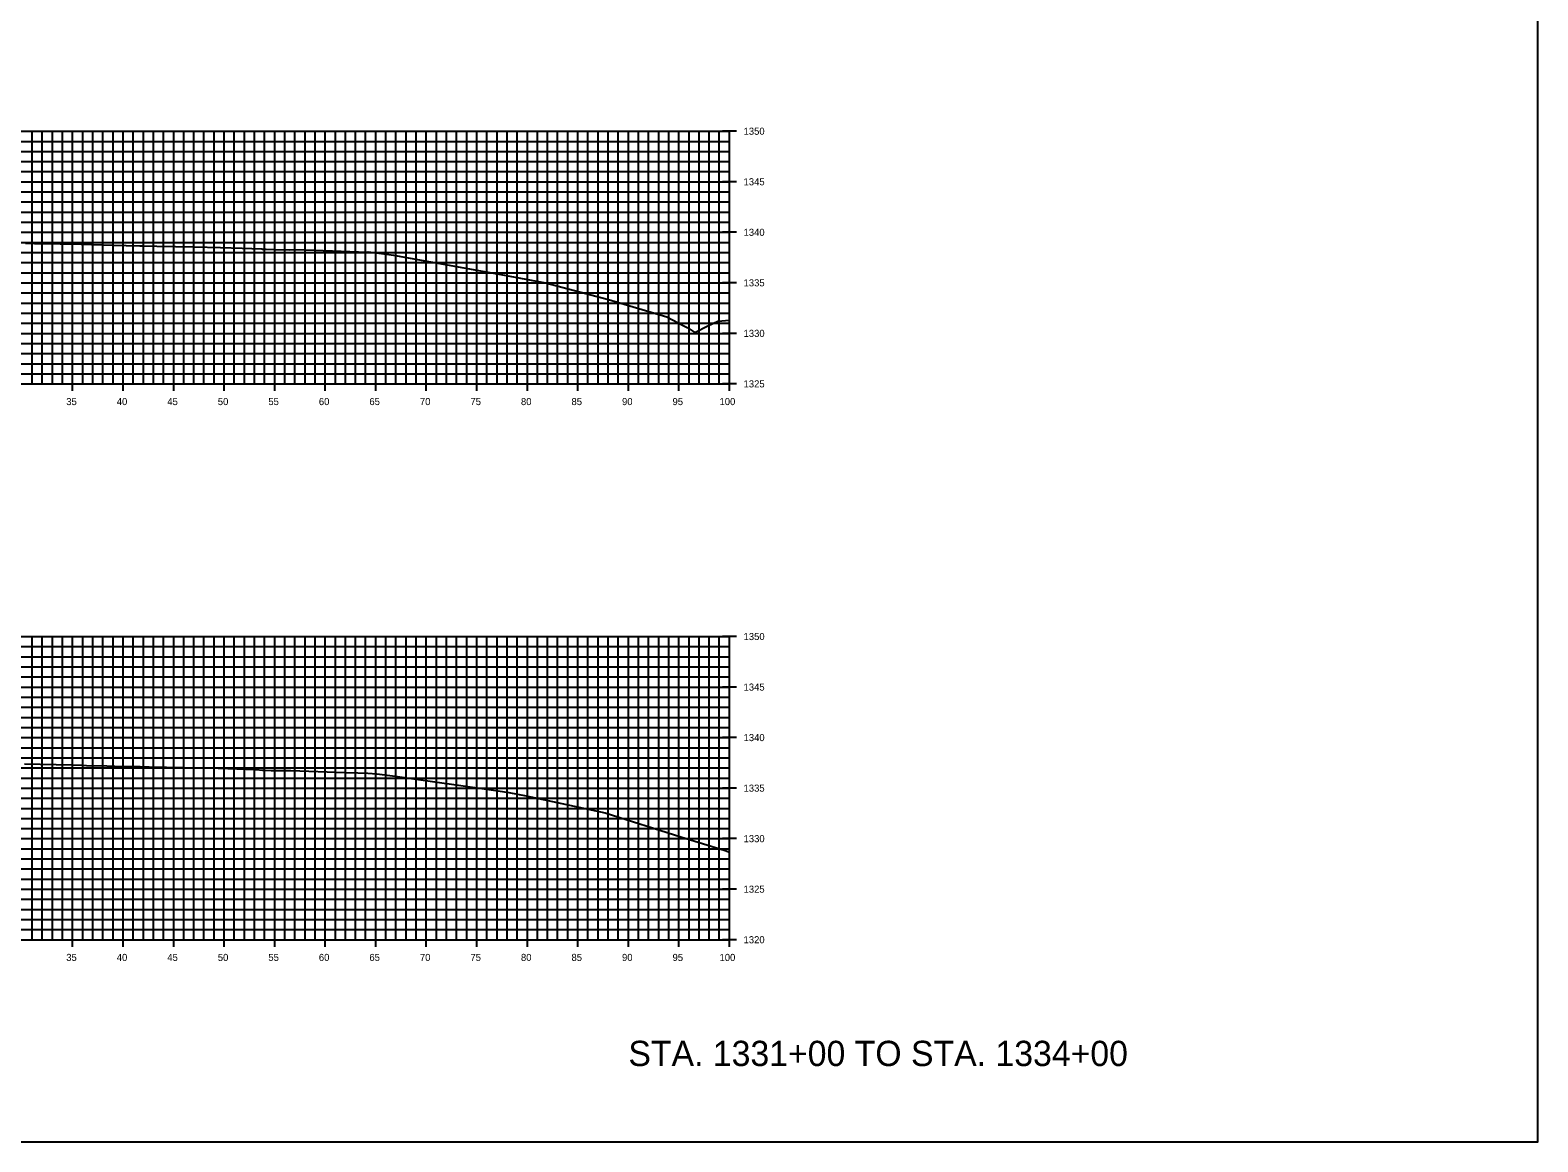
# Model space of a CAD drawing. Extents: x 674939 to 678919, y 750652 to 765176.
# Drawn here: x 678769.3 to 678918.5, y 752072.6 to 752182.6 of the extents above; entities that cross this region are included whole.
import ezdxf

# ---------------------------------------------------------------- set-up
doc = ezdxf.new("R2010")
doc.units = 0
for name, color, linetype in [('Level 10', 7, 'Continuous'), ('Level 20', 7, 'Continuous'), ('Level 21', 7, 'Continuous'), ('Level 4', 7, 'Continuous'), ('Level 8', 7, 'Continuous'), ('Level 9', 7, 'Continuous')]:
    doc.layers.add(name, color=color, linetype=linetype)

msp = doc.modelspace()

# ---------------------------------------------------------------- linework, layer by layer
at = {"layer": 'Level 10'}
for points in [[(678768.88, 752161.47), (678769.77, 752161.44), (678772.29, 752161.4), (678774.37, 752161.36), (678777.49, 752161.28), (678780.18, 752161.22), (678780.38, 752161.21), (678780.58, 752161.2), (678781.88, 752161.18), (678785.56, 752161.11), (678788.18, 752161.06), (678790.31, 752160.98), (678792.23, 752160.9), (678792.27, 752160.9), (678792.32, 752160.89), (678792.68, 752160.87), (678793.47, 752160.85), (678794.98, 752160.83), (678795.58, 752160.84), (678799.26, 752160.7), (678802.68, 752160.59), (678802.78, 752160.6), (678804.1, 752160.45), (678805.27, 752160.3), (678815.9, 752158.37), (678820.34, 752157.54), (678826.56, 752155.91), (678832.32, 752154.19), (678834.03, 752153.3), (678834.42, 752153.09), (678835.1, 752152.64), (678836.39, 752153.3), (678837.37, 752153.76), (678838.53, 752153.85)], [(678768.77, 752109.94), (678773.45, 752109.85), (678774.57, 752109.83), (678774.9, 752109.8), (678776.91, 752109.75), (678777.7, 752109.74), (678780.2, 752109.68), (678781.09, 752109.66), (678787.95, 752109.52), (678788.9, 752109.49), (678791.57, 752109.39), (678791.69, 752109.38), (678792.31, 752109.34), (678792.45, 752109.33), (678793.17, 752109.28), (678793.47, 752109.28), (678795.14, 752109.28), (678800.49, 752109.11), (678801.76, 752109.06), (678802.74, 752109.04), (678803.64, 752108.95), (678805.46, 752108.75), (678815.65, 752107.27), (678816.69, 752107.12), (678818.41, 752106.78), (678826.22, 752105.12), (678833.72, 752102.73), (678838.1, 752101.38), (678838.53, 752101.23)]]:
    msp.add_lwpolyline(points, dxfattribs=at)
at = {"layer": 'Level 20'}
for p, q in [((678638.53, 752172.55), (678838.53, 752172.55)), ((678638.53, 752171.55), (678838.53, 752171.55)), ((678769.53, 752147.55), (678769.53, 752172.55)), ((678770.53, 752147.55), (678770.53, 752172.55)), ((678771.53, 752147.55), (678771.53, 752172.55)), ((678772.53, 752147.55), (678772.53, 752172.55)), ((678773.53, 752147.55), (678773.53, 752172.55)), ((678774.53, 752147.55), (678774.53, 752172.55)), ((678775.53, 752147.55), (678775.53, 752172.55)), ((678776.53, 752147.55), (678776.53, 752172.55)), ((678777.53, 752147.55), (678777.53, 752172.55)), ((678778.53, 752147.55), (678778.53, 752172.55)), ((678779.53, 752147.55), (678779.53, 752172.55)), ((678780.53, 752147.55), (678780.53, 752172.55)), ((678781.53, 752147.55), (678781.53, 752172.55)), ((678782.53, 752147.55), (678782.53, 752172.55)), ((678783.53, 752147.55), (678783.53, 752172.55)), ((678784.53, 752147.55), (678784.53, 752172.55)), ((678785.53, 752147.55), (678785.53, 752172.55)), ((678786.53, 752147.55), (678786.53, 752172.55)), ((678787.53, 752147.55), (678787.53, 752172.55)), ((678788.53, 752147.55), (678788.53, 752172.55)), ((678789.53, 752147.55), (678789.53, 752172.55)), ((678790.53, 752147.55), (678790.53, 752172.55)), ((678791.53, 752147.55), (678791.53, 752172.55)), ((678792.53, 752147.55), (678792.53, 752172.55)), ((678793.53, 752147.55), (678793.53, 752172.55)), ((678794.53, 752147.55), (678794.53, 752172.55)), ((678795.53, 752147.55), (678795.53, 752172.55)), ((678796.53, 752147.55), (678796.53, 752172.55)), ((678797.53, 752147.55), (678797.53, 752172.55)), ((678798.53, 752147.55), (678798.53, 752172.55)), ((678799.53, 752147.55), (678799.53, 752172.55)), ((678800.53, 752147.55), (678800.53, 752172.55)), ((678801.53, 752147.55), (678801.53, 752172.55)), ((678802.53, 752147.55), (678802.53, 752172.55)), ((678803.53, 752147.55), (678803.53, 752172.55)), ((678804.53, 752147.55), (678804.53, 752172.55)), ((678805.53, 752147.55), (678805.53, 752172.55)), ((678806.53, 752147.55), (678806.53, 752172.55)), ((678807.53, 752147.55), (678807.53, 752172.55)), ((678808.53, 752147.55), (678808.53, 752172.55)), ((678809.53, 752147.55), (678809.53, 752172.55)), ((678810.53, 752147.55), (678810.53, 752172.55)), ((678811.53, 752147.55), (678811.53, 752172.55)), ((678812.53, 752147.55), (678812.53, 752172.55)), ((678813.53, 752147.55), (678813.53, 752172.55)), ((678814.53, 752147.55), (678814.53, 752172.55)), ((678815.53, 752147.55), (678815.53, 752172.55)), ((678816.53, 752147.55), (678816.53, 752172.55)), ((678817.53, 752147.55), (678817.53, 752172.55)), ((678818.53, 752147.55), (678818.53, 752172.55)), ((678819.53, 752147.55), (678819.53, 752172.55)), ((678820.53, 752147.55), (678820.53, 752172.55)), ((678821.53, 752147.55), (678821.53, 752172.55)), ((678822.53, 752147.55), (678822.53, 752172.55)), ((678823.53, 752147.55), (678823.53, 752172.55)), ((678824.53, 752147.55), (678824.53, 752172.55)), ((678825.53, 752147.55), (678825.53, 752172.55)), ((678826.53, 752147.55), (678826.53, 752172.55)), ((678827.53, 752147.55), (678827.53, 752172.55)), ((678828.53, 752147.55), (678828.53, 752172.55)), ((678829.53, 752147.55), (678829.53, 752172.55)), ((678830.53, 752147.55), (678830.53, 752172.55)), ((678831.53, 752147.55), (678831.53, 752172.55)), ((678832.53, 752147.55), (678832.53, 752172.55)), ((678833.53, 752147.55), (678833.53, 752172.55)), ((678834.53, 752147.55), (678834.53, 752172.55)), ((678835.53, 752147.55), (678835.53, 752172.55)), ((678836.53, 752147.55), (678836.53, 752172.55)), ((678837.53, 752147.55), (678837.53, 752172.55)), ((678838.53, 752147.55), (678838.53, 752172.55)), ((678638.53, 752170.55), (678838.53, 752170.55)), ((678638.53, 752169.55), (678838.53, 752169.55)), ((678638.53, 752168.55), (678838.53, 752168.55)), ((678638.53, 752167.55), (678838.53, 752167.55)), ((678638.53, 752166.55), (678838.53, 752166.55)), ((678638.53, 752165.55), (678838.53, 752165.55)), ((678638.53, 752164.55), (678838.53, 752164.55)), ((678638.53, 752163.55), (678838.53, 752163.55)), ((678638.53, 752162.55), (678838.53, 752162.55)), ((678638.53, 752161.55), (678838.53, 752161.55)), ((678638.53, 752160.55), (678838.53, 752160.55)), ((678638.53, 752159.55), (678838.53, 752159.55)), ((678638.53, 752158.55), (678838.53, 752158.55)), ((678638.53, 752157.55), (678838.53, 752157.55)), ((678638.53, 752156.55), (678838.53, 752156.55)), ((678638.53, 752155.55), (678838.53, 752155.55)), ((678638.53, 752154.55), (678838.53, 752154.55)), ((678638.53, 752153.55), (678838.53, 752153.55)), ((678638.53, 752152.55), (678838.53, 752152.55)), ((678638.53, 752151.55), (678838.53, 752151.55)), ((678638.53, 752150.55), (678838.53, 752150.55)), ((678638.53, 752149.55), (678838.53, 752149.55)), ((678638.53, 752148.55), (678838.53, 752148.55)), ((678638.53, 752147.55), (678838.53, 752147.55)), ((678638.53, 752122.55), (678838.53, 752122.55)), ((678769.53, 752092.55), (678769.53, 752122.55)), ((678770.53, 752092.55), (678770.53, 752122.55)), ((678771.53, 752092.55), (678771.53, 752122.55)), ((678772.53, 752092.55), (678772.53, 752122.55)), ((678773.53, 752092.55), (678773.53, 752122.55)), ((678774.53, 752092.55), (678774.53, 752122.55)), ((678775.53, 752092.55), (678775.53, 752122.55)), ((678776.53, 752092.55), (678776.53, 752122.55)), ((678777.53, 752092.55), (678777.53, 752122.55)), ((678778.53, 752092.55), (678778.53, 752122.55)), ((678779.53, 752092.55), (678779.53, 752122.55)), ((678780.53, 752092.55), (678780.53, 752122.55)), ((678781.53, 752092.55), (678781.53, 752122.55)), ((678782.53, 752092.55), (678782.53, 752122.55)), ((678783.53, 752092.55), (678783.53, 752122.55)), ((678784.53, 752092.55), (678784.53, 752122.55)), ((678785.53, 752092.55), (678785.53, 752122.55)), ((678786.53, 752092.55), (678786.53, 752122.55)), ((678787.53, 752092.55), (678787.53, 752122.55)), ((678788.53, 752092.55), (678788.53, 752122.55)), ((678789.53, 752092.55), (678789.53, 752122.55)), ((678790.53, 752092.55), (678790.53, 752122.55)), ((678791.53, 752092.55), (678791.53, 752122.55)), ((678792.53, 752092.55), (678792.53, 752122.55)), ((678793.53, 752092.55), (678793.53, 752122.55)), ((678794.53, 752092.55), (678794.53, 752122.55)), ((678795.53, 752092.55), (678795.53, 752122.55)), ((678796.53, 752092.55), (678796.53, 752122.55)), ((678797.53, 752092.55), (678797.53, 752122.55)), ((678798.53, 752092.55), (678798.53, 752122.55)), ((678799.53, 752092.55), (678799.53, 752122.55)), ((678800.53, 752092.55), (678800.53, 752122.55)), ((678801.53, 752092.55), (678801.53, 752122.55)), ((678802.53, 752092.55), (678802.53, 752122.55)), ((678803.53, 752092.55), (678803.53, 752122.55)), ((678804.53, 752092.55), (678804.53, 752122.55)), ((678805.53, 752092.55), (678805.53, 752122.55)), ((678806.53, 752092.55), (678806.53, 752122.55)), ((678807.53, 752092.55), (678807.53, 752122.55)), ((678808.53, 752092.55), (678808.53, 752122.55)), ((678809.53, 752092.55), (678809.53, 752122.55)), ((678810.53, 752092.55), (678810.53, 752122.55)), ((678811.53, 752092.55), (678811.53, 752122.55)), ((678812.53, 752092.55), (678812.53, 752122.55)), ((678813.53, 752092.55), (678813.53, 752122.55)), ((678814.53, 752092.55), (678814.53, 752122.55)), ((678815.53, 752092.55), (678815.53, 752122.55)), ((678816.53, 752092.55), (678816.53, 752122.55)), ((678817.53, 752092.55), (678817.53, 752122.55)), ((678818.53, 752092.55), (678818.53, 752122.55)), ((678819.53, 752092.55), (678819.53, 752122.55)), ((678820.53, 752092.55), (678820.53, 752122.55)), ((678821.53, 752092.55), (678821.53, 752122.55)), ((678822.53, 752092.55), (678822.53, 752122.55)), ((678823.53, 752092.55), (678823.53, 752122.55)), ((678824.53, 752092.55), (678824.53, 752122.55)), ((678825.53, 752092.55), (678825.53, 752122.55)), ((678826.53, 752092.55), (678826.53, 752122.55)), ((678827.53, 752092.55), (678827.53, 752122.55)), ((678828.53, 752092.55), (678828.53, 752122.55)), ((678829.53, 752092.55), (678829.53, 752122.55)), ((678830.53, 752092.55), (678830.53, 752122.55)), ((678831.53, 752092.55), (678831.53, 752122.55)), ((678832.53, 752092.55), (678832.53, 752122.55)), ((678833.53, 752092.55), (678833.53, 752122.55)), ((678834.53, 752092.55), (678834.53, 752122.55)), ((678835.53, 752092.55), (678835.53, 752122.55)), ((678836.53, 752092.55), (678836.53, 752122.55)), ((678837.53, 752092.55), (678837.53, 752122.55)), ((678838.53, 752092.55), (678838.53, 752122.55)), ((678638.53, 752121.55), (678838.53, 752121.55)), ((678638.53, 752120.55), (678838.53, 752120.55)), ((678638.53, 752119.55), (678838.53, 752119.55)), ((678638.53, 752118.55), (678838.53, 752118.55)), ((678638.53, 752117.55), (678838.53, 752117.55)), ((678638.53, 752116.55), (678838.53, 752116.55)), ((678638.53, 752115.55), (678838.53, 752115.55)), ((678638.53, 752114.55), (678838.53, 752114.55)), ((678638.53, 752113.55), (678838.53, 752113.55)), ((678638.53, 752112.55), (678838.53, 752112.55)), ((678638.53, 752111.55), (678838.53, 752111.55)), ((678638.53, 752110.55), (678838.53, 752110.55)), ((678638.53, 752109.55), (678838.53, 752109.55)), ((678638.53, 752108.55), (678838.53, 752108.55)), ((678638.53, 752107.55), (678838.53, 752107.55)), ((678638.53, 752106.55), (678838.53, 752106.55)), ((678638.53, 752105.55), (678838.53, 752105.55)), ((678638.53, 752104.55), (678838.53, 752104.55)), ((678638.53, 752103.55), (678838.53, 752103.55)), ((678638.53, 752102.55), (678838.53, 752102.55)), ((678638.53, 752101.55), (678838.53, 752101.55)), ((678638.53, 752100.55), (678838.53, 752100.55)), ((678638.53, 752099.55), (678838.53, 752099.55)), ((678638.53, 752098.55), (678838.53, 752098.55)), ((678638.53, 752097.55), (678838.53, 752097.55)), ((678638.53, 752096.55), (678838.53, 752096.55)), ((678638.53, 752095.55), (678838.53, 752095.55)), ((678638.53, 752094.55), (678838.53, 752094.55)), ((678638.53, 752093.55), (678838.53, 752093.55)), ((678638.53, 752092.55), (678838.53, 752092.55))]:
    msp.add_line(p, q, dxfattribs=at)
at = {"layer": 'Level 4'}
msp.add_lwpolyline([(678578.53, 752072.55), (678918.53, 752072.55), (678918.53, 752292.55), (678578.53, 752292.55)], close=True, dxfattribs=at)
at = {"layer": 'Level 8'}
for p, q in [((678839.23, 752172.55), (678837.83, 752172.55)), ((678838.53, 752147.55), (678838.53, 752172.55)), ((678839.23, 752167.55), (678837.83, 752167.55)), ((678839.23, 752162.55), (678837.83, 752162.55)), ((678839.23, 752157.55), (678837.83, 752157.55)), ((678839.23, 752152.55), (678837.83, 752152.55)), ((678773.53, 752146.85), (678773.53, 752148.25)), ((678778.53, 752146.85), (678778.53, 752148.25)), ((678783.53, 752146.85), (678783.53, 752148.25)), ((678788.53, 752146.85), (678788.53, 752148.25)), ((678793.53, 752146.85), (678793.53, 752148.25)), ((678798.53, 752146.85), (678798.53, 752148.25)), ((678803.53, 752146.85), (678803.53, 752148.25)), ((678808.53, 752146.85), (678808.53, 752148.25)), ((678813.53, 752146.85), (678813.53, 752148.25)), ((678818.53, 752146.85), (678818.53, 752148.25)), ((678823.53, 752146.85), (678823.53, 752148.25)), ((678828.53, 752146.85), (678828.53, 752148.25)), ((678833.53, 752146.85), (678833.53, 752148.25)), ((678838.53, 752146.85), (678838.53, 752148.25)), ((678638.53, 752147.55), (678838.53, 752147.55)), ((678839.23, 752147.55), (678837.83, 752147.55)), ((678839.23, 752122.55), (678837.83, 752122.55)), ((678838.53, 752092.55), (678838.53, 752122.55)), ((678839.23, 752117.55), (678837.83, 752117.55)), ((678839.23, 752112.55), (678837.83, 752112.55)), ((678839.23, 752107.55), (678837.83, 752107.55)), ((678839.23, 752102.55), (678837.83, 752102.55)), ((678839.23, 752097.55), (678837.83, 752097.55)), ((678638.53, 752092.55), (678838.53, 752092.55)), ((678773.53, 752091.85), (678773.53, 752093.25)), ((678778.53, 752091.85), (678778.53, 752093.25)), ((678783.53, 752091.85), (678783.53, 752093.25)), ((678788.53, 752091.85), (678788.53, 752093.25)), ((678793.53, 752091.85), (678793.53, 752093.25)), ((678798.53, 752091.85), (678798.53, 752093.25)), ((678803.53, 752091.85), (678803.53, 752093.25)), ((678808.53, 752091.85), (678808.53, 752093.25)), ((678813.53, 752091.85), (678813.53, 752093.25)), ((678818.53, 752091.85), (678818.53, 752093.25)), ((678823.53, 752091.85), (678823.53, 752093.25)), ((678828.53, 752091.85), (678828.53, 752093.25)), ((678833.53, 752091.85), (678833.53, 752093.25)), ((678839.23, 752092.55), (678837.83, 752092.55)), ((678838.53, 752091.85), (678838.53, 752093.25))]:
    msp.add_line(p, q, dxfattribs=at)

# ---------------------------------------------------------------- texts
at = {"layer": 'Level 21'}
msp.add_text('STA. 1331+00 TO STA. 1334+00', height=2.5, dxfattribs=at).set_placement((678828.53, 752080.05))
at = {"layer": 'Level 9'}
for s, p in [('1350', (678839.93, 752172.2)), ('1345', (678839.93, 752167.2)), ('1340', (678839.93, 752162.2)), ('1335', (678839.93, 752157.2)), ('1330', (678839.93, 752152.2)), ('1325', (678839.93, 752147.2)), ('35', (678772.9, 752145.45)), ('40', (678777.9, 752145.45)), ('45', (678782.9, 752145.45)), ('50', (678787.9, 752145.45)), ('55', (678792.9, 752145.45)), ('60', (678797.9, 752145.45)), ('65', (678802.9, 752145.45)), ('70', (678807.9, 752145.45)), ('75', (678812.9, 752145.45)), ('80', (678817.9, 752145.45)), ('85', (678822.9, 752145.45)), ('90', (678827.9, 752145.45)), ('95', (678832.9, 752145.45)), ('100', (678837.55, 752145.45)), ('1350', (678839.93, 752122.2)), ('1345', (678839.93, 752117.2)), ('1340', (678839.93, 752112.2)), ('1335', (678839.93, 752107.2)), ('1330', (678839.93, 752102.2)), ('1325', (678839.93, 752097.2)), ('1320', (678839.93, 752092.2)), ('35', (678772.9, 752090.45)), ('40', (678777.9, 752090.45)), ('45', (678782.9, 752090.45)), ('50', (678787.9, 752090.45)), ('55', (678792.9, 752090.45)), ('60', (678797.9, 752090.45)), ('65', (678802.9, 752090.45)), ('70', (678807.9, 752090.45)), ('75', (678812.9, 752090.45)), ('80', (678817.9, 752090.45)), ('85', (678822.9, 752090.45)), ('90', (678827.9, 752090.45)), ('95', (678832.9, 752090.45)), ('100', (678837.55, 752090.45))]:
    msp.add_text(s, height=0.7, dxfattribs=at).set_placement(p)

doc.saveas('drawing.dxf')
